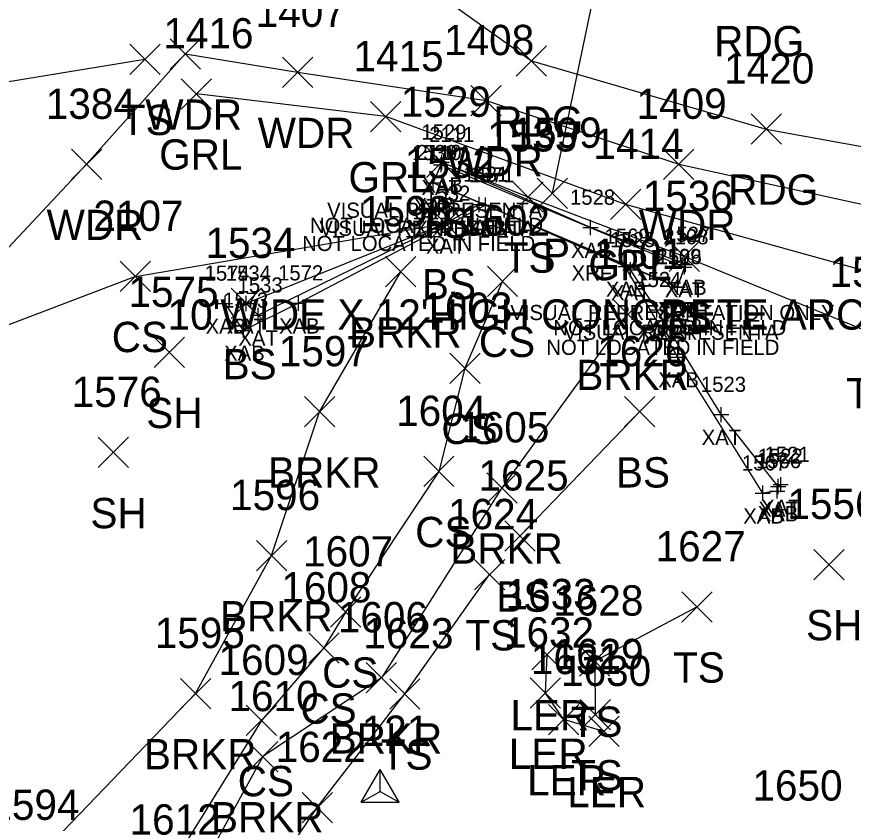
# Model space of a CAD drawing. Extents: x 1526508 to 1531550, y 369926 to 373082.
# Drawn here: x 1531020.1 to 1531075.3, y 370058.1 to 370111.3 of the extents above; entities that cross this region are included whole.
import ezdxf

# ---------------------------------------------------------------- set-up
doc = ezdxf.new("R2010")
doc.units = 0
for name, color, linetype in [('B_A', 7, 'Continuous'), ('B_C', 7, 'Continuous'), ('B_I', 7, 'Continuous'), ('B_TIC', 7, 'Continuous'), ('BSUBM', 7, 'Continuous'), ('C_I', 7, 'Continuous'), ('CPSM', 7, 'Continuous'), ('D_A', 7, 'Continuous'), ('D_C', 7, 'Continuous'), ('D_I', 7, 'Continuous'), ('D_TIC', 7, 'Continuous'), ('DCP', 7, 'Continuous'), ('L_A', 7, 'Continuous'), ('L_I', 7, 'Continuous'), ('L_TIC', 7, 'Continuous'), ('LARO', 7, 'Continuous'), ('LAWA', 7, 'Continuous'), ('LAWE', 7, 'Continuous'), ('LELB', 7, 'Continuous'), ('P_A', 7, 'Continuous'), ('P_I', 7, 'Continuous'), ('P_TIC', 7, 'Continuous'), ('PEU', 7, 'Continuous'), ('R_A', 7, 'Continuous'), ('R_I', 7, 'Continuous'), ('R_TIC', 7, 'Continuous'), ('RGR', 7, 'Continuous')]:
    doc.layers.add(name, color=color, linetype=linetype)

msp = doc.modelspace()

# ---------------------------------------------------------------- linework, layer by layer
at = {"layer": 'B_TIC'}
for p, q in [((1531048.143, 370101.582), (1531048.218, 370101.582)), ((1531048.189, 370101.743), (1531048.265, 370101.743)), ((1531047.614, 370100.384), (1531047.69, 370100.384)), ((1531047.626, 370100.39), (1531047.702, 370100.39)), ((1531050.669, 370098.957), (1531050.744, 370098.957)), ((1531051.067, 370098.913), (1531051.143, 370098.913)), ((1531048.44, 370097.704), (1531048.516, 370097.704)), ((1531058.001, 370097.439), (1531058.077, 370097.439)), ((1531060.303, 370094.871), (1531060.379, 370094.871)), ((1531064.203, 370094.831), (1531064.279, 370094.831)), ((1531064.274, 370094.994), (1531064.349, 370094.994)), ((1531060.649, 370094.643), (1531060.724, 370094.643)), ((1531063.742, 370093.533), (1531063.818, 370093.533)), ((1531063.751, 370093.514), (1531063.826, 370093.514)), ((1531033.885, 370092.433), (1531033.961, 370092.433)), ((1531035.286, 370092.43), (1531035.361, 370092.43)), ((1531038.735, 370092.445), (1531038.811, 370092.445)), ((1531036.062, 370091.647), (1531036.137, 370091.647)), ((1531062.376, 370092.011), (1531062.452, 370092.011)), ((1531035.107, 370090.652), (1531035.182, 370090.652)), ((1531063.759, 370088.895), (1531063.835, 370088.895)), ((1531066.641, 370085.095), (1531066.716, 370085.095)), ((1531070.56, 370080.476), (1531070.636, 370080.476)), ((1531070.327, 370080.054), (1531070.403, 370080.054)), ((1531070.387, 370080.351), (1531070.463, 370080.351)), ((1531069.371, 370079.907), (1531069.447, 370079.907))]:
    msp.add_line(p, q, dxfattribs=at)
for points in [[(1531048.139, 370101.082), (1531048.139, 370102.082)], [(1531048.186, 370101.243), (1531048.186, 370102.243)], [(1531047.639, 370101.582), (1531048.639, 370101.582)], [(1531047.686, 370101.743), (1531048.686, 370101.743)], [(1531047.623, 370099.89), (1531047.623, 370100.89)], [(1531047.111, 370100.384), (1531048.111, 370100.384)], [(1531047.123, 370100.39), (1531048.123, 370100.39)], [(1531047.611, 370099.884), (1531047.611, 370100.884)], [(1531050.665, 370098.457), (1531050.665, 370099.457)], [(1531051.064, 370098.413), (1531051.064, 370099.413)], [(1531050.165, 370098.957), (1531051.165, 370098.957)], [(1531050.564, 370098.913), (1531051.564, 370098.913)], [(1531048.437, 370097.204), (1531048.437, 370098.204)], [(1531047.937, 370097.704), (1531048.937, 370097.704)], [(1531057.998, 370096.939), (1531057.998, 370097.939)], [(1531057.498, 370097.439), (1531058.498, 370097.439)], [(1531060.3, 370094.371), (1531060.3, 370095.371)], [(1531064.27, 370094.494), (1531064.27, 370095.494)], [(1531059.8, 370094.871), (1531060.8, 370094.871)], [(1531060.645, 370094.143), (1531060.645, 370095.143)], [(1531063.7, 370094.831), (1531064.7, 370094.831)], [(1531063.77, 370094.994), (1531064.77, 370094.994)], [(1531064.2, 370094.331), (1531064.2, 370095.331)], [(1531060.145, 370094.643), (1531061.145, 370094.643)], [(1531063.739, 370093.033), (1531063.739, 370094.033)], [(1531063.747, 370093.014), (1531063.747, 370094.014)], [(1531063.239, 370093.533), (1531064.239, 370093.533)], [(1531063.247, 370093.514), (1531064.247, 370093.514)], [(1531033.882, 370091.933), (1531033.882, 370092.933)], [(1531035.282, 370091.93), (1531035.282, 370092.93)], [(1531038.732, 370091.945), (1531038.732, 370092.945)], [(1531033.382, 370092.433), (1531034.382, 370092.433)], [(1531034.782, 370092.43), (1531035.782, 370092.43)], [(1531036.058, 370091.147), (1531036.058, 370092.147)], [(1531038.232, 370092.445), (1531039.232, 370092.445)], [(1531062.373, 370091.511), (1531062.373, 370092.511)], [(1531035.558, 370091.647), (1531036.558, 370091.647)], [(1531061.873, 370092.011), (1531062.873, 370092.011)], [(1531035.103, 370090.152), (1531035.103, 370091.152)], [(1531034.603, 370090.652), (1531035.603, 370090.652)], [(1531063.756, 370088.395), (1531063.756, 370089.395)], [(1531063.256, 370088.895), (1531064.256, 370088.895)], [(1531066.637, 370084.595), (1531066.637, 370085.595)], [(1531066.137, 370085.095), (1531067.137, 370085.095)], [(1531070.057, 370080.476), (1531071.057, 370080.476)], [(1531070.324, 370079.554), (1531070.324, 370080.554)], [(1531070.384, 370079.851), (1531070.384, 370080.851)], [(1531070.557, 370079.976), (1531070.557, 370080.976)], [(1531069.368, 370079.407), (1531069.368, 370080.407)], [(1531069.824, 370080.054), (1531070.824, 370080.054)], [(1531069.884, 370080.351), (1531070.884, 370080.351)], [(1531068.868, 370079.907), (1531069.868, 370079.907)]]:
    msp.add_lwpolyline(points, dxfattribs=at)
at = {"layer": 'BSUBM'}
for points in [[(1531063.747, 370093.514), (1531064.27, 370094.994), (1531057.998, 370097.439), (1531048.186, 370101.743), (1531047.611, 370100.384)], [(1531064.2, 370094.831), (1531063.739, 370093.533), (1531047.623, 370100.39), (1531048.139, 370101.582)], [(1531048.139, 370101.582), (1531064.2, 370094.831)], [(1531047.611, 370100.384), (1531063.747, 370093.514)], [(1531070.324, 370080.054), (1531069.368, 370079.907), (1531063.756, 370088.895), (1531060.3, 370094.871), (1531051.064, 370098.913), (1531038.732, 370092.445), (1531035.103, 370090.652), (1531033.882, 370092.433)], [(1531050.665, 370098.957), (1531048.437, 370097.704), (1531036.058, 370091.647), (1531035.282, 370092.43)], [(1531070.557, 370080.476), (1531070.384, 370080.351), (1531066.637, 370085.095), (1531062.373, 370092.011), (1531060.645, 370094.643)]]:
    msp.add_lwpolyline(points, dxfattribs=at)
at = {"layer": 'CPSM'}
for p, q in [((1531042.877, 370059.515), (1531044.127, 370061.68)), ((1531045.377, 370059.515), (1531044.127, 370061.68)), ((1531044.127, 370060.237), (1531044.127, 370061.68)), ((1531042.877, 370059.515), (1531044.127, 370060.237)), ((1531044.127, 370060.237), (1531044.127, 370060.237)), ((1531044.127, 370060.237), (1531045.377, 370059.515)), ((1531042.877, 370059.515), (1531045.377, 370059.515))]:
    msp.add_line(p, q, dxfattribs=at)
at = {"layer": 'D_TIC'}
for points in [[(1531054.491, 370098.698), (1531056.491, 370100.698)], [(1531056.491, 370098.698), (1531054.491, 370100.698)]]:
    msp.add_lwpolyline(points, dxfattribs=at)
at = {"layer": 'DCP'}
msp.add_lwpolyline([(1531055.491, 370099.698), (1531060.382, 370123.096), (1531085.607, 370183.89)], dxfattribs=at)
at = {"layer": 'L_TIC'}
for points in [[(1531030.255, 370107.889), (1531032.255, 370109.889)], [(1531032.255, 370107.889), (1531030.255, 370109.889)], [(1531027.597, 370107.539), (1531029.597, 370109.539)], [(1531029.597, 370107.539), (1531027.597, 370109.539)], [(1531037.675, 370106.681), (1531039.675, 370108.681)], [(1531039.675, 370106.681), (1531037.675, 370108.681)], [(1531050.109, 370104.813), (1531052.109, 370106.813)], [(1531052.109, 370104.813), (1531050.109, 370106.813)], [(1531023.743, 370100.609), (1531025.743, 370102.609)], [(1531025.743, 370100.609), (1531023.743, 370102.609)], [(1531047.186, 370100.743), (1531049.186, 370102.743)], [(1531049.186, 370100.743), (1531047.186, 370102.743)], [(1531062.824, 370100.61), (1531064.824, 370102.61)], [(1531064.824, 370100.61), (1531062.824, 370102.61)], [(1531052.871, 370098.456), (1531054.871, 370100.456)], [(1531054.871, 370098.456), (1531052.871, 370100.456)], [(1531047.437, 370096.704), (1531049.437, 370098.704)], [(1531049.437, 370096.704), (1531047.437, 370098.704)], [(1531063.198, 370094.529), (1531065.198, 370096.529)], [(1531065.198, 370094.529), (1531063.198, 370096.529)], [(1531044.475, 370093.519), (1531046.475, 370095.519)], [(1531046.475, 370093.519), (1531044.475, 370095.519)], [(1531026.964, 370093.218), (1531028.964, 370095.218)], [(1531028.964, 370093.218), (1531026.964, 370095.218)], [(1531051.195, 370092.898), (1531053.195, 370094.898)], [(1531053.195, 370092.898), (1531051.195, 370094.898)], [(1531034.282, 370091.43), (1531036.282, 370093.43)], [(1531036.282, 370091.43), (1531034.282, 370093.43)], [(1531059.475, 370090.712), (1531061.475, 370092.712)], [(1531061.475, 370090.712), (1531059.475, 370092.712)], [(1531029.198, 370088.204), (1531031.198, 370090.204)], [(1531031.198, 370088.204), (1531029.198, 370090.204)], [(1531048.718, 370087.151), (1531050.718, 370089.151)], [(1531050.718, 370087.151), (1531048.718, 370089.151)], [(1531039.124, 370084.283), (1531041.124, 370086.283)], [(1531041.124, 370084.283), (1531039.124, 370086.283)], [(1531060.242, 370084.284), (1531062.242, 370086.284)], [(1531062.242, 370084.284), (1531060.242, 370086.284)], [(1531025.508, 370081.599), (1531027.508, 370083.599)], [(1531027.508, 370081.599), (1531025.508, 370083.599)], [(1531046.993, 370080.349), (1531048.993, 370082.349)], [(1531048.993, 370080.349), (1531046.993, 370082.349)], [(1531051.156, 370079.261), (1531053.156, 370081.261)], [(1531053.156, 370079.261), (1531051.156, 370081.261)], [(1531052.35, 370076.086), (1531054.35, 370078.086)], [(1531054.35, 370076.086), (1531052.35, 370078.086)], [(1531035.959, 370074.792), (1531037.959, 370076.792)], [(1531037.959, 370074.792), (1531035.959, 370076.792)], [(1531072.744, 370074.203), (1531074.744, 370076.203)], [(1531074.744, 370074.203), (1531072.744, 370076.203)], [(1531050.339, 370073.535), (1531052.339, 370075.535)], [(1531052.339, 370073.535), (1531050.339, 370075.535)], [(1531064.039, 370071.409), (1531066.039, 370073.409)], [(1531066.039, 370071.409), (1531064.039, 370073.409)], [(1531040.848, 370071.074), (1531042.848, 370073.074)], [(1531042.848, 370071.074), (1531040.848, 370073.074)], [(1531039.413, 370068.701), (1531041.413, 370070.701)], [(1531041.413, 370068.701), (1531039.413, 370070.701)], [(1531054.136, 370068.255), (1531056.136, 370070.255)], [(1531056.136, 370068.255), (1531054.136, 370070.255)], [(1531057.285, 370067.833), (1531059.285, 370069.833)], [(1531059.285, 370067.833), (1531057.285, 370069.833)], [(1531043.198, 370066.732), (1531045.198, 370068.732)], [(1531045.198, 370066.732), (1531043.198, 370068.732)], [(1531030.936, 370065.689), (1531032.936, 370067.689)], [(1531032.936, 370065.689), (1531030.936, 370067.689)], [(1531044.749, 370065.67), (1531046.749, 370067.67)], [(1531046.749, 370065.67), (1531044.749, 370067.67)], [(1531054.03, 370065.722), (1531056.03, 370067.722)], [(1531056.03, 370065.722), (1531054.03, 370067.722)], [(1531057.313, 370064.298), (1531059.313, 370066.298)], [(1531059.313, 370064.298), (1531057.313, 370066.298)], [(1531035.278, 370063.915), (1531037.278, 370065.915)], [(1531037.278, 370063.915), (1531035.278, 370065.915)], [(1531055.238, 370063.97), (1531057.238, 370065.97)], [(1531057.238, 370063.97), (1531055.238, 370065.97)], [(1531057.884, 370063.193), (1531059.884, 370065.193)], [(1531059.884, 370063.193), (1531057.884, 370065.193)], [(1531035.367, 370061.528), (1531037.367, 370063.528)], [(1531037.367, 370061.528), (1531035.367, 370063.528)], [(1531038.965, 370058.168), (1531040.965, 370060.168)], [(1531040.965, 370058.168), (1531038.965, 370060.168)]]:
    msp.add_lwpolyline(points, dxfattribs=at)
at = {"layer": 'LARO'}
msp.add_lwpolyline([(1531058.884, 370064.193), (1531056.238, 370064.97), (1531055.03, 370066.722), (1531055.136, 370069.255)], dxfattribs=at)
at = {"layer": 'LAWA'}
msp.add_lwpolyline([(1530968.161, 370037.392), (1530979.881, 370048.994), (1530990.042, 370057.094), (1531002.64, 370070.867), (1531012.129, 370088.176), (1531024.743, 370101.609), (1531031.255, 370108.889), (1531038.675, 370107.681), (1531051.109, 370105.813), (1531063.824, 370101.61), (1531080.52, 370097.978), (1531114.388, 370088.681)], dxfattribs=at)
at = {"layer": 'LAWE'}
for points in [[(1531019.456, 370025.658), (1531015.092, 370031.681), (1531017.735, 370042.895), (1531021.022, 370055.353), (1531031.936, 370066.689), (1531036.959, 370075.792), (1531040.124, 370085.283), (1531045.475, 370094.519)], [(1531060.475, 370091.712), (1531052.156, 370080.261), (1531044.198, 370067.732), (1531036.367, 370062.528), (1531030.602, 370052.039), (1531024.354, 370038.592), (1531026.106, 370027.484), (1531033.741, 370021.245), (1531037.461, 370014.917), (1531034.276, 370006.285), (1531036.574, 370000.952), (1531037.909, 369989.716), (1531028.612, 369973.066), (1531021.32, 369966.868), (1531020.147, 369956.358), (1531019.718, 369949.927), (1531016.167, 369945.616)]]:
    msp.add_lwpolyline(points, dxfattribs=at)
at = {"layer": 'LELB'}
for points in [[(1531005.583, 370105.584), (1531015.011, 370106.334), (1531028.597, 370108.539)], [(1531048.186, 370101.743), (1531053.871, 370099.456), (1531064.198, 370095.529), (1531076.472, 370090.509), (1531092.092, 370084.5), (1531103.911, 370077.569)], [(1531027.964, 370094.218), (1531048.437, 370097.704)], [(1531048.437, 370097.704), (1531035.282, 370092.43)], [(1531052.195, 370093.898), (1531049.718, 370088.151), (1531047.993, 370081.349), (1531041.848, 370072.074), (1531040.413, 370069.701), (1531036.278, 370064.915), (1531029.752, 370054.384), (1531023.869, 370046.306), (1531022.036, 370040.527), (1531022.957, 370027.162), (1531029.889, 370020.999), (1531033.283, 370015.536), (1531028.189, 370006.244), (1531029.192, 369995.782), (1531030.035, 369991.3), (1531027.529, 369979.919), (1531018.741, 369970.401), (1531013.395, 369964.149), (1531009.139, 369955.011)], [(1531027.964, 370094.218), (1531012.129, 370088.176)], [(1531053.35, 370077.086), (1531061.242, 370085.284)], [(1531028.743, 370031.349), (1531029.514, 370037.051), (1531029.641, 370042.031), (1531033.568, 370049.701), (1531039.965, 370059.168), (1531045.749, 370066.67), (1531051.339, 370074.535)], [(1531065.039, 370072.409), (1531058.285, 370068.833), (1531058.313, 370065.298)]]:
    msp.add_lwpolyline(points, dxfattribs=at)
at = {"layer": 'P_TIC'}
for points in [[(1531053.099, 370107.435), (1531055.099, 370109.435)], [(1531055.099, 370107.435), (1531053.099, 370109.435)], [(1531068.601, 370102.939), (1531070.601, 370104.939)], [(1531070.601, 370102.939), (1531068.601, 370104.939)]]:
    msp.add_lwpolyline(points, dxfattribs=at)
at = {"layer": 'PEU'}
msp.add_lwpolyline([(1531023.29, 370127.706), (1531040.68, 370117.999), (1531054.099, 370108.435), (1531069.601, 370103.939), (1531084.917, 370101.163), (1531104.196, 370096.573), (1531116.34, 370088.254), (1531119.549, 370080.003), (1531124.942, 370058.759)], dxfattribs=at)
at = {"layer": 'R_TIC'}
for points in [[(1531030.992, 370105.258), (1531032.992, 370107.258)], [(1531032.992, 370105.258), (1531030.992, 370107.258)], [(1531043.484, 370103.756), (1531045.484, 370105.756)], [(1531045.484, 370103.756), (1531043.484, 370105.756)], [(1531059.32, 370097.965), (1531061.32, 370099.965)], [(1531061.32, 370097.965), (1531059.32, 370099.965)]]:
    msp.add_lwpolyline(points, dxfattribs=at)
at = {"layer": 'RGR'}
msp.add_lwpolyline([(1531112.461, 370087.357), (1531084.985, 370092.112), (1531060.32, 370098.965), (1531044.484, 370104.756), (1531031.992, 370106.258)], dxfattribs=at)

# ---------------------------------------------------------------- texts
at = {"layer": 'B_A'}
for s, p in [('XAT', (1531046.844, 370099.582)), ('XAB', (1531046.906, 370099.743)), ('XAT', (1531046.327, 370098.39)), ('XAB', (1531046.331, 370098.384)), ('XAT', (1531049.37, 370096.957)), ('XAB', (1531049.784, 370096.913)), ('XAT', (1531047.141, 370095.704)), ('XAB', (1531056.718, 370095.439)), ('XAB', (1531059.02, 370092.871)), ('XAT', (1531062.904, 370092.831)), ('XAB', (1531062.991, 370092.994)), ('XAT', (1531059.35, 370092.643)), ('XAT', (1531062.444, 370091.533)), ('XAB', (1531062.468, 370091.514)), ('XAB', (1531032.602, 370090.433)), ('XAT', (1531033.987, 370090.43)), ('XAB', (1531037.452, 370090.445)), ('XAT', (1531061.078, 370090.011)), ('XAT', (1531034.763, 370089.647)), ('XAB', (1531033.824, 370088.652)), ('XAB', (1531062.476, 370086.895)), ('XAT', (1531065.342, 370083.095)), ('XAT', (1531069.262, 370078.476)), ('XAB', (1531068.088, 370077.907)), ('XAB', (1531069.044, 370078.054)), ('XAT', (1531069.088, 370078.351))]:
    msp.add_text(s, height=1, dxfattribs=at).set_placement(p)
at = {"layer": 'B_C'}
for s, p in [('XRF', (1531046.946, 370098.243)), ('VISUAL REPRESENTA', (1531040.623, 370098.082)), ('NOT LOCATED IN FIELD', (1531039.489, 370097.082)), ('VISUAL REPRESENTA', (1531040.107, 370096.89)), ('XRF', (1531046.371, 370096.884)), ('NOT LOCATED IN FIELD', (1531038.973, 370095.89)), ('XRF', (1531056.758, 370093.939)), ('VISUAL REPRESENTATION ONLY', (1531052.711, 370091.331)), ('XRF', (1531063.03, 370091.494)), ('NOT LOCATED IN FIELD', (1531055.55, 370090.331)), ('VISUAL REPRESENTA', (1531056.223, 370090.033)), ('XRF', (1531062.507, 370090.014)), ('NOT LOCATED IN FIELD', (1531055.089, 370089.033))]:
    msp.add_text(s, height=1, dxfattribs=at).set_placement(p)
at = {"layer": 'B_I'}
for s, p in [('1529', (1531046.836, 370103.243)), ('2111', (1531047.36, 370103.082)), ('1530', (1531046.221, 370101.884)), ('2110', (1531046.516, 370101.89)), ('1531', (1531049.602, 370100.457)), ('1571', (1531050.001, 370100.413)), ('1532', (1531047.09, 370099.204)), ('1528', (1531056.651, 370098.939)), ('1569', (1531058.926, 370096.371)), ('1525', (1531059.299, 370096.143)), ('2108', (1531062.814, 370096.331)), ('1527', (1531062.924, 370096.494)), ('2109', (1531062.349, 370095.033)), ('1526', (1531062.373, 370095.014)), ('1574', (1531032.535, 370093.933)), ('1534', (1531033.936, 370093.93)), ('1572', (1531037.385, 370093.945)), ('1524', (1531061.026, 370093.511)), ('1533', (1531034.712, 370093.147)), ('1573', (1531033.757, 370092.152)), ('1568', (1531062.386, 370090.395)), ('1523', (1531065.291, 370086.595)), ('1522', (1531069.037, 370081.851)), ('1521', (1531069.494, 370081.976)), ('1567', (1531067.998, 370081.407)), ('1566', (1531068.926, 370081.554))]:
    msp.add_text(s, height=1, dxfattribs=at).set_placement(p)
at = {"layer": 'C_I'}
msp.add_text('121', height=2, dxfattribs=at).set_placement((1531042.899, 370063.237))
at = {"layer": 'D_A'}
msp.add_text('P', height=2, dxfattribs=at).set_placement((1531054.869, 370094.698))
at = {"layer": 'D_C'}
msp.add_text("10'WIDE X 12'HIGH CONCRETE ARCH", height=2, dxfattribs=at).set_placement((1531030.089, 370090.698))
at = {"layer": 'D_I'}
msp.add_text('1599', height=2, dxfattribs=at).set_placement((1531052.79, 370102.698))
at = {"layer": 'L_A'}
for s, p in [('WDR', (1531028.618, 370103.889)), ('TS', (1531027.007, 370103.539)), ('WDR', (1531036.037, 370102.681)), ('WDR', (1531048.471, 370100.813)), ('TS', (1531046.595, 370096.743)), ('WDR', (1531022.106, 370096.609)), ('WDR', (1531061.186, 370096.61)), ('TS', (1531052.28, 370094.456)), ('BS', (1531046.877, 370092.704)), ('TS', (1531062.607, 370090.529)), ('BRKR', (1531042.066, 370089.519)), ('CS', (1531026.405, 370089.218)), ('CS', (1531050.636, 370088.898)), ('BS', (1531033.723, 370087.43)), ('BRKR', (1531057.066, 370086.712)), ('TS', (1531074.882, 370085.509)), ('SH', (1531028.686, 370084.204)), ('CS', (1531048.159, 370083.151)), ('BRKR', (1531036.714, 370080.283)), ('BS', (1531059.683, 370080.284)), ('SH', (1531024.996, 370077.599)), ('CS', (1531046.434, 370076.349)), ('BRKR', (1531048.747, 370075.261)), ('BS', (1531051.791, 370072.086)), ('BRKR', (1531033.549, 370070.792)), ('SH', (1531072.232, 370070.203)), ('TS', (1531049.748, 370069.535)), ('TS', (1531063.449, 370067.409)), ('CS', (1531040.289, 370067.074)), ('CS', (1531038.854, 370064.701)), ('LER', (1531052.719, 370064.255)), ('TS', (1531056.694, 370063.833)), ('BRKR', (1531040.788, 370062.732)), ('BRKR', (1531028.526, 370061.689)), ('TS', (1531044.159, 370061.67)), ('LER', (1531052.613, 370061.722)), ('TS', (1531056.722, 370060.298)), ('CS', (1531034.719, 370059.915)), ('LER', (1531053.821, 370059.97)), ('LER', (1531056.466, 370059.193)), ('BRKR', (1531032.957, 370057.528))]:
    msp.add_text(s, height=2, dxfattribs=at).set_placement(p)
at = {"layer": 'L_I'}
for s, p in [('1407', (1531035.904, 370110.681)), ('1408', (1531048.337, 370108.813)), ('1384', (1531022.05, 370104.609)), ('1529', (1531045.485, 370104.743)), ('1409', (1531061.044, 370104.61)), ('1535', (1531051.178, 370102.456)), ('1532', (1531045.744, 370100.704)), ('1536', (1531061.45, 370098.529)), ('2107', (1531025.192, 370097.218)), ('1598', (1531042.782, 370097.519)), ('1602', (1531049.376, 370096.898)), ('1534', (1531032.59, 370095.43)), ('1601', (1531058.223, 370094.712)), ('1537', (1531073.779, 370093.509)), ('1575', (1531027.505, 370092.204)), ('1603', (1531046.899, 370091.151)), ('1597', (1531037.431, 370088.283)), ('1626', (1531058.447, 370088.284)), ('1576', (1531023.76, 370085.599)), ('1604', (1531045.174, 370084.349)), ('1605', (1531049.337, 370083.261)), ('1625', (1531050.61, 370080.086)), ('1596', (1531034.211, 370078.792)), ('1556', (1531070.996, 370078.203)), ('1624', (1531048.599, 370077.535)), ('1627', (1531062.299, 370075.409)), ('1607', (1531039.029, 370075.074)), ('1608', (1531037.594, 370072.701)), ('1633', (1531052.396, 370072.255)), ('1628', (1531055.544, 370071.833)), ('1606', (1531041.324, 370070.732)), ('1595', (1531029.243, 370069.689)), ('1623', (1531043.009, 370069.67)), ('1632', (1531052.29, 370069.722)), ('1631', (1531054.065, 370067.97)), ('1629', (1531055.564, 370068.298)), ('1609', (1531033.452, 370067.915)), ('1630', (1531056.057, 370067.193)), ('1610', (1531034.107, 370065.528)), ('1622', (1531037.225, 370062.168)), ('1650', (1531068.691, 370059.629)), ('1594', (1531018.329, 370058.353)), ('1612', (1531027.579, 370057.384))]:
    msp.add_text(s, height=2, dxfattribs=at).set_placement(p)
at = {"layer": 'P_A'}
for p in [(1531066.164, 370108.738), (1531051.587, 370103.435), (1531067.089, 370098.939)]:
    msp.add_text('RDG', height=2, dxfattribs=at).set_placement(p)
at = {"layer": 'P_I'}
msp.add_text('1420', height=2, dxfattribs=at).set_placement((1531066.822, 370106.939))
at = {"layer": 'R_A'}
for p in [(1531029.536, 370101.258), (1531042.027, 370099.756), (1531057.863, 370093.965)]:
    msp.add_text('GRL', height=2, dxfattribs=at).set_placement(p)
at = {"layer": 'R_I'}
for s, p in [('1416', (1531029.811, 370109.258)), ('1415', (1531042.358, 370107.756)), ('1414', (1531058.194, 370101.965))]:
    msp.add_text(s, height=2, dxfattribs=at).set_placement(p)

doc.saveas('drawing.dxf')
